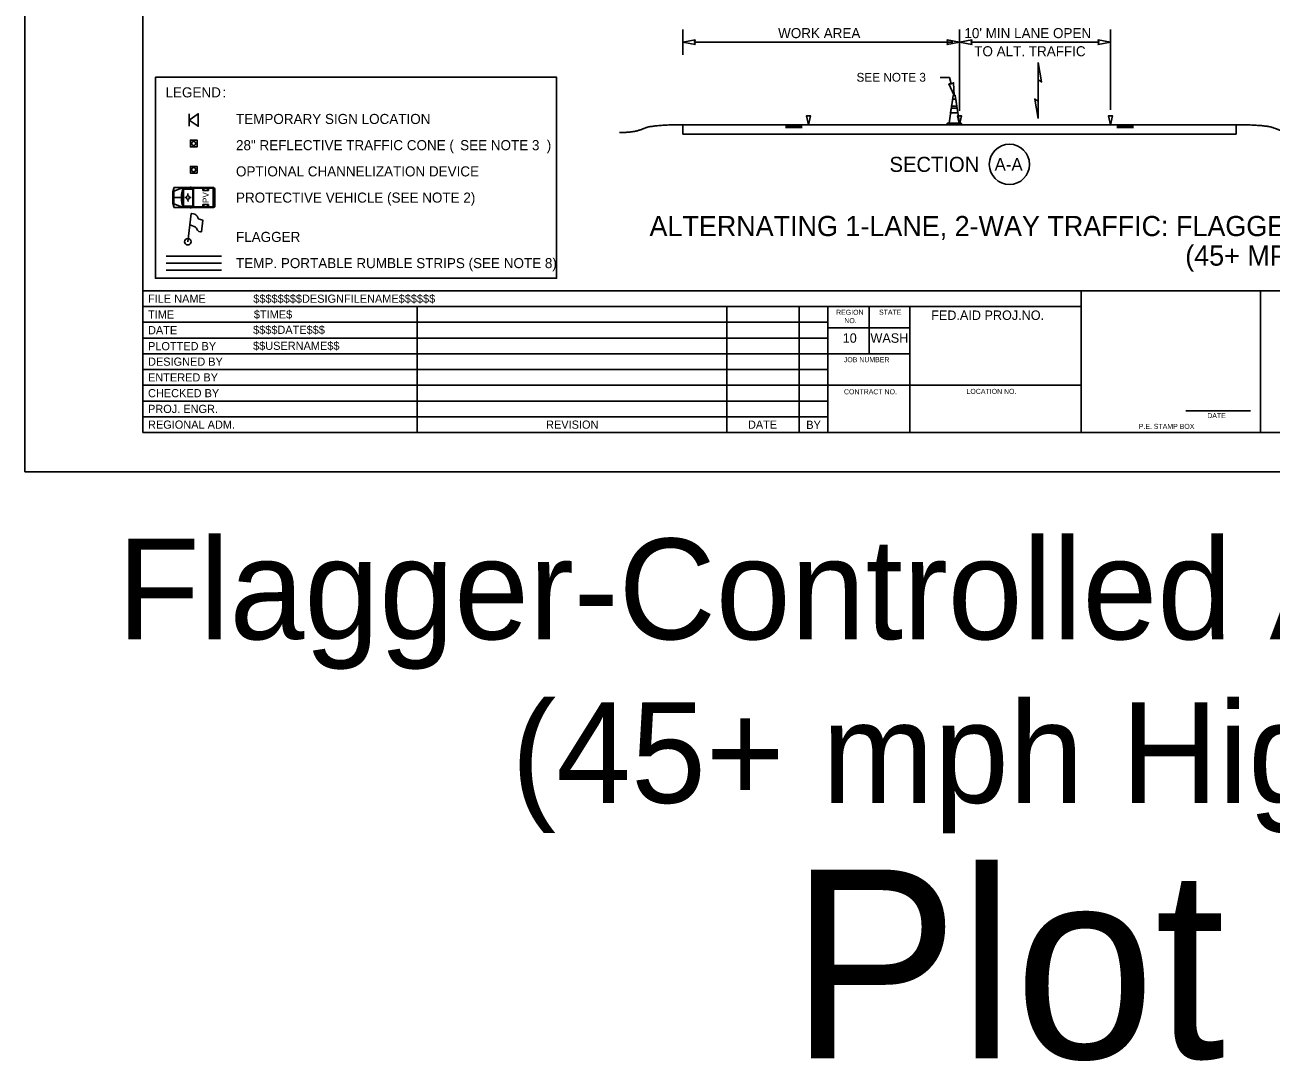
# Model space of a CAD drawing. Extents: x 99999.1 to 100095.7, y 99995 to 100010.7.
# Drawn here: x 99999.06 to 100008.97, y 99995.01 to 100003.24 of the extents above; entities that cross this region are included whole.
import ezdxf

# ---------------------------------------------------------------- set-up
doc = ezdxf.new("R2010")
doc.units = 0
for name, color, linetype in [('SH_DE_DetailHeading1Text', 7, 'Continuous'), ('SH_GI_PlotLimits', 7, 'Continuous'), ('SH_GI_SheetBorder', 7, 'Continuous'), ('SH_GI_SheetLocationText', 7, 'Continuous'), ('SH_GI_SheetTextInCells', 7, 'Continuous'), ('SH_GI_TitleBlockText', 7, 'Continuous'), ('TR_WZ_FlaggingStation', 7, 'Continuous'), ('TR_WZ_PortableSignMountBlk-Org', 7, 'Continuous'), ('TR_WZ_ProtectiveVehicle', 7, 'Continuous'), ('TR_WZ_TrafficCone', 7, 'Continuous'), ('TR_WZ_TrafficConeElev', 7, 'Continuous'), ('TR_WZ_WorkZoneDetails', 7, 'Continuous'), ('TR_WZ_WorkZoneTextCurrent', 7, 'Continuous')]:
    doc.layers.add(name, color=color, linetype=linetype)

msp = doc.modelspace()

# ---------------------------------------------------------------- linework, layer by layer
at = {"layer": 'SH_GI_PlotLimits'}
msp.add_lwpolyline([(99999.0625, 99999.6875), (100016.0625, 99999.6875), (100016.0625, 100010.6875), (99999.0625, 100010.6875)], close=True, dxfattribs=at)
at = {"layer": 'SH_GI_SheetBorder'}
for p, q in [((100000, 100010.375), (100000, 100000)), ((100000, 100001.1259), (100015.75, 100001.1259)), ((100007.4566, 100000), (100007.4566, 100001.1259)), ((100008.8828, 100000), (100008.8828, 100001.1259)), ((100000, 100001.0008), (100007.4566, 100001.0008)), ((100002.179, 100001.0008), (100002.179, 100000)), ((100004.641, 100001.0008), (100004.641, 100000)), ((100005.2164, 100001.0008), (100005.2164, 100000)), ((100005.4451, 100001.0008), (100005.4451, 100000)), ((100005.7719, 100000.6255), (100005.7719, 100001.0008)), ((100006.0956, 100000), (100006.0956, 100001.0008)), ((100000, 100000.8757), (100002.1821, 100000.8757)), ((100002.1821, 100000.8757), (100005.4466, 100000.8757)), ((100006.0958, 100000.831), (100005.4466, 100000.831)), ((100000, 100000.7506), (100002.1821, 100000.7506)), ((100002.1821, 100000.7506), (100005.4466, 100000.7506)), ((100000, 100000.6255), (100005.4466, 100000.6255)), ((100006.0958, 100000.6255), (100005.4466, 100000.6255)), ((100000, 100000.5004), (100005.4466, 100000.5004)), ((100000, 100000.3753), (100005.4466, 100000.3753)), ((100007.4566, 100000.3753), (100005.4466, 100000.3753)), ((100000, 100000.2502), (100005.4466, 100000.2502)), ((100008.2903, 100000.1733), (100008.802, 100000.1733)), ((100000, 100000.1251), (100005.4466, 100000.1251)), ((100000, 100000), (100015.75, 100000))]:
    msp.add_line(p, q, dxfattribs=at)
at = {"layer": 'TR_WZ_FlaggingStation'}
for p, q in [((100000.3571, 100001.5162), (100000.3828, 100001.7409)), ((100000.3723, 100001.6497), (100000.3828, 100001.7412)), ((100000.4771, 100001.6869), (100000.4665, 100001.5932)), ((100000.3723, 100001.6497), (100000.3723, 100001.6497))]:
    msp.add_line(p, q, dxfattribs=at)
for points in [[(100000.3828, 100001.7412), (100000.3874, 100001.7402), (100000.4016, 100001.7374), (100000.4127, 100001.7341), (100000.4204, 100001.7292), (100000.4273, 100001.7254), (100000.4318, 100001.72), (100000.4352, 100001.7137), (100000.4356, 100001.7087), (100000.4399, 100001.7014), (100000.4486, 100001.6954), (100000.4585, 100001.6912), (100000.4771, 100001.6869)], [(100000.4665, 100001.5932), (100000.46, 100001.5943), (100000.4458, 100001.598), (100000.4333, 100001.6064), (100000.4281, 100001.6149), (100000.425, 100001.6231), (100000.4177, 100001.6318), (100000.4089, 100001.6368), (100000.395, 100001.6425), (100000.3723, 100001.6497)]]:
    msp.add_lwpolyline(points, dxfattribs=at)
msp.add_circle((100000.3571, 100001.5162), 0.026, dxfattribs=at)
at = {"layer": 'TR_WZ_PortableSignMountBlk-Org'}
msp.add_line((100000.3682, 100002.433), (100000.3682, 100002.533), dxfattribs=at)
msp.add_lwpolyline([(100000.3682, 100002.4829), (100000.44, 100002.533), (100000.44, 100002.433)], close=True, dxfattribs=at)
at = {"layer": 'TR_WZ_ProtectiveVehicle'}
for p, q in [((100000.245, 100001.9466), (100000.2376, 100001.9143)), ((100000.2376, 100001.9143), (100000.2376, 100001.8189)), ((100000.245, 100001.9466), (100000.245, 100001.7866)), ((100000.245, 100001.9466), (100000.3962, 100001.9466)), ((100000.245, 100001.9173), (100000.3206, 100001.9466)), ((100000.245, 100001.8666), (100000.3058, 100001.8666)), ((100000.3206, 100001.9466), (100000.3206, 100001.7866)), ((100000.322, 100001.9466), (100000.322, 100001.7866)), ((100000.322, 100001.9466), (100000.3316, 100001.9342)), ((100000.322, 100001.9342), (100000.3962, 100001.9342)), ((100000.3341, 100001.8667), (100000.3442, 100001.8667)), ((100000.3582, 100001.8983), (100000.3582, 100001.8854)), ((100000.3695, 100001.8663), (100000.3695, 100001.8663)), ((100000.3829, 100001.866), (100000.371, 100001.8663)), ((100000.3756, 100001.9489), (100000.3846, 100001.9489)), ((100000.3962, 100001.9466), (100000.3962, 100001.7866)), ((100000.5629, 100001.9466), (100000.3984, 100001.9466)), ((100000.3984, 100001.9466), (100000.3984, 100001.7866)), ((100000.5583, 100001.9402), (100000.403, 100001.9402)), ((100000.403, 100001.9402), (100000.403, 100001.793)), ((100000.4772, 100001.9402), (100000.4772, 100001.9218)), ((100000.5212, 100001.9218), (100000.4772, 100001.9218)), ((100000.4852, 100001.9402), (100000.4852, 100001.9218)), ((100000.5124, 100001.9402), (100000.5124, 100001.9218)), ((100000.5212, 100001.9402), (100000.5212, 100001.9218)), ((100000.5583, 100001.9402), (100000.5583, 100001.793)), ((100000.5629, 100001.9466), (100000.5629, 100001.7866)), ((100000.5671, 100001.944), (100000.5635, 100001.944)), ((100000.5635, 100001.944), (100000.5635, 100001.7892)), ((100000.5706, 100001.8779), (100000.5635, 100001.8749)), ((100000.5706, 100001.8553), (100000.5635, 100001.8583)), ((100000.5687, 100001.8666), (100000.5654, 100001.8666)), ((100000.5671, 100001.8689), (100000.5671, 100001.8643)), ((100000.5706, 100001.9391), (100000.5706, 100001.7941)), ((100000.245, 100001.7866), (100000.2376, 100001.8189)), ((100000.245, 100001.8159), (100000.3206, 100001.7866)), ((100000.245, 100001.7866), (100000.3962, 100001.7866)), ((100000.322, 100001.799), (100000.3962, 100001.799)), ((100000.3299, 100001.799), (100000.322, 100001.7866)), ((100000.3588, 100001.8358), (100000.3586, 100001.8479)), ((100000.3756, 100001.7843), (100000.3846, 100001.7843)), ((100000.5629, 100001.7866), (100000.3984, 100001.7866)), ((100000.5583, 100001.793), (100000.403, 100001.793)), ((100000.4772, 100001.793), (100000.4772, 100001.8114)), ((100000.5212, 100001.8114), (100000.4772, 100001.8114)), ((100000.4852, 100001.793), (100000.4852, 100001.8114)), ((100000.5124, 100001.793), (100000.5124, 100001.8114)), ((100000.5212, 100001.793), (100000.5212, 100001.8114)), ((100000.5671, 100001.7892), (100000.5635, 100001.7892))]:
    msp.add_line(p, q, dxfattribs=at)
for centre, major_axis, start_param, end_param in [((100000.4286, 100001.8666), (0, -0.1679), 4.215667, 5.208926), ((100000.5671, 100001.9391), (0, 0.00488), 4.712389, 6.283185), ((100000.5671, 100001.7941), (0, -0.00488), 0, 1.570796)]:
    msp.add_ellipse(centre, major_axis=major_axis, ratio=0.73155, start_param=start_param, end_param=end_param, dxfattribs=at)
for centre, major_axis in [((100000.3582, 100001.8666), (0, 0.0154)), ((100000.5671, 100001.8666), (0, 0.00225))]:
    msp.add_ellipse(centre, major_axis=major_axis, ratio=0.73155, dxfattribs=at)
at = {"layer": 'TR_WZ_TrafficCone'}
for points in [[(100000.3775, 100002.3231), (100000.4308, 100002.3231), (100000.4308, 100002.2698), (100000.3775, 100002.2698), (100000.3775, 100002.3231)], [(100000.3775, 100002.2698), (100000.4308, 100002.2698), (100000.4308, 100002.3231), (100000.3775, 100002.3231), (100000.3775, 100002.2698)], [(100000.3775, 100002.1148), (100000.4308, 100002.1148), (100000.4308, 100002.0615), (100000.3775, 100002.0615), (100000.3775, 100002.1148)], [(100000.3775, 100002.0615), (100000.4308, 100002.0615), (100000.4308, 100002.1148), (100000.3775, 100002.1148), (100000.3775, 100002.0615)]]:
    msp.add_lwpolyline(points, dxfattribs=at)
for centre in [(100000.4041, 100002.2964), (100000.4041, 100002.0881)]:
    msp.add_circle(centre, 0.0167, dxfattribs=at)
at = {"layer": 'TR_WZ_TrafficConeElev'}
for p, q in [((100006.4363, 100002.6476), (100006.428, 100002.5934)), ((100006.4616, 100002.6476), (100006.4363, 100002.6476)), ((100006.4699, 100002.5934), (100006.4616, 100002.6476)), ((100006.4255, 100002.5768), (100006.4197, 100002.5393)), ((100006.4724, 100002.5768), (100006.4255, 100002.5768)), ((100006.428, 100002.5934), (100006.4699, 100002.5934)), ((100006.4782, 100002.5393), (100006.4724, 100002.5768)), ((100006.3953, 100002.458), (100006.3911, 100002.4538)), ((100006.3911, 100002.4538), (100006.3911, 100002.4455)), ((100006.4073, 100002.458), (100006.3953, 100002.458)), ((100006.4197, 100002.5393), (100006.4782, 100002.5393)), ((100006.5068, 100002.4538), (100006.5026, 100002.458)), ((100006.5068, 100002.4455), (100006.5068, 100002.4538)), ((100006.3911, 100002.4455), (100006.5068, 100002.4455))]:
    msp.add_line(p, q, dxfattribs=at)
msp.add_lwpolyline([(100006.4073, 100002.458), (100006.4906, 100002.458), (100006.4568, 100002.6788), (100006.4411, 100002.6788)], close=True, dxfattribs=at)
msp.add_lwpolyline([(100006.4073, 100002.458), (100006.4906, 100002.458), (100006.4568, 100002.6788), (100006.4411, 100002.6788)], close=True, dxfattribs=at)
msp.add_lwpolyline([(100006.5026, 100002.458), (100006.4906, 100002.458), (100006.4073, 100002.458)], dxfattribs=at)
at = {"layer": 'TR_WZ_WorkZoneDetails'}
for p, q in [((100004.2907, 100003.0015), (100004.2907, 100003.2015)), ((100006.4907, 100002.5552), (100006.4907, 100003.2015)), ((100007.6907, 100002.5652), (100007.6907, 100003.2015)), ((100006.4387, 100003.1015), (100004.3844, 100003.1015)), ((100007.597, 100003.1015), (100006.5844, 100003.1015)), ((100006.3358, 100002.8215), (100006.412, 100002.8215)), ((100006.4255, 100002.7696), (100006.412, 100002.8215)), ((100007.1157, 100002.8019), (100007.1157, 100002.6331)), ((100007.1157, 100002.6331), (100007.1157, 100002.8019)), ((100004.2907, 100002.4454), (100004.2907, 100002.3704)), ((100008.6907, 100002.4454), (100004.2907, 100002.4454)), ((100008.6907, 100002.3704), (100004.2907, 100002.3704)), ((100005.1077, 100002.4402), (100005.2407, 100002.4402)), ((100005.1077, 100002.4346), (100005.2407, 100002.4346)), ((100005.1077, 100002.4289), (100005.2407, 100002.4289)), ((100005.1077, 100002.4237), (100005.2407, 100002.4237)), ((100007.8737, 100002.4398), (100007.7407, 100002.4398)), ((100007.8737, 100002.4342), (100007.7407, 100002.4342)), ((100007.8737, 100002.4285), (100007.7407, 100002.4285)), ((100007.8737, 100002.4233), (100007.7407, 100002.4233)), ((100008.6907, 100002.4454), (100008.6907, 100002.3704)), ((100000.6241, 100001.4012), (100000.1841, 100001.4012)), ((100000.6241, 100001.3463), (100000.1841, 100001.3463)), ((100000.6241, 100001.2906), (100000.1841, 100001.2906))]:
    msp.add_line(p, q, dxfattribs=at)
for points in [[(100004.2907, 100003.1015), (100004.389, 100003.0822), (100004.3844, 100003.1015), (100004.389, 100003.1208)], [(100006.4907, 100003.1015), (100006.3924, 100003.0822), (100006.397, 100003.1015), (100006.3924, 100003.1208)], [(100006.4907, 100003.1015), (100006.589, 100003.0822), (100006.5844, 100003.1015), (100006.589, 100003.1208)], [(100007.6907, 100003.1015), (100007.5924, 100003.0822), (100007.597, 100003.1015), (100007.5924, 100003.1208)], [(100007.1157, 100002.9395), (100007.1427, 100002.7863), (100007.1157, 100002.8019)], [(100006.449, 100002.6788), (100006.4057, 100002.7692), (100006.4255, 100002.7696), (100006.443, 100002.7788)], [(100007.1157, 100002.4954), (100007.0887, 100002.6487), (100007.1157, 100002.6331)], [(100005.2907, 100002.4454), (100005.274, 100002.5152), (100005.3073, 100002.5152)], [(100006.4907, 100002.4454), (100006.474, 100002.5152), (100006.5074, 100002.5152)], [(100007.6907, 100002.4454), (100007.674, 100002.5152), (100007.7073, 100002.5152)]]:
    msp.add_lwpolyline(points, close=True, dxfattribs=at)
for points in [[(100005.3073, 100002.5152), (100005.274, 100002.5152), (100005.2907, 100002.4454), (100005.3073, 100002.5152)], [(100006.5074, 100002.5152), (100006.474, 100002.5152), (100006.4907, 100002.4454), (100006.5074, 100002.5152)], [(100007.7073, 100002.5152), (100007.674, 100002.5152), (100007.6907, 100002.4454), (100007.7073, 100002.5152)]]:
    msp.add_lwpolyline(points, dxfattribs=at)
msp.add_circle((100006.8872, 100002.1305), 0.16, dxfattribs=at)
for points in [[(100004.2907, 100002.4454), (100004.0395, 100002.4454), (100003.914, 100002.3833), (100003.7886, 100002.3833)], [(100008.6907, 100002.4454), (100008.9419, 100002.4456), (100009.0674, 100002.3835), (100009.1928, 100002.3836)]]:
    msp.add_open_spline(points, degree=2, dxfattribs=at)
at = {"layer": 'TR_WZ_WorkZoneTextCurrent'}
msp.add_lwpolyline([(100000.1, 100002.8227), (100003.2886, 100002.8227), (100003.2886, 100001.2259), (100000.1, 100001.2259)], close=True, dxfattribs=at)

# ---------------------------------------------------------------- texts
at = {"layer": 'SH_DE_DetailHeading1Text'}
for s, p in [('ALTERNATING 1-LANE, 2-WAY TRAFFIC: FLAGGER-CONTROLLED + TEMPORARY RUMBLE STRIPS', (100004.0265, 100001.5606)), ('(45+ MPH HIGHWAYS)', (100008.2846, 100001.3259))]:
    msp.add_text(s, height=0.16, rotation=360, dxfattribs=at).set_placement(p)
at = {"layer": 'SH_GI_SheetLocationText'}
for s, height, p in [('Flagger-Controlled Alt Traffic + RS', 0.8, (99999.7975, 99998.3571)), ('(45+ mph Highways)', 0.8, (100002.9286, 99997.0571)), ('Plot 1', 1.5, (100005.1448, 99995.0267))]:
    msp.add_text(s, height=height, dxfattribs=at).set_placement(p)
at = {"layer": 'SH_GI_SheetTextInCells'}
for s, height, p in [('FILE NAME', 0.06505, (100000.041, 100001.0308)), ('TIME', 0.06505, (100000.041, 100000.9057)), ('REGION', 0.04003, (100005.5099, 100000.9352)), ('STATE', 0.04003, (100005.8511, 100000.9357)), ('FED.AID PROJ.NO.', 0.07506, (100006.2652, 100000.8945)), ('NO.', 0.04003, (100005.5752, 100000.869)), ('DATE', 0.06505, (100000.041, 100000.7806)), ('10', 0.07506, (100005.5621, 100000.7131)), ('WASH', 0.07506, (100005.7826, 100000.7131)), ('PLOTTED BY', 0.06505, (100000.041, 100000.6538)), ('DESIGNED BY', 0.065052, (100000.041, 100000.5304)), ('JOB NUMBER', 0.04003, (100005.5712, 100000.5587)), ('ENTERED BY', 0.06505, (100000.041, 100000.4053)), ('CHECKED BY', 0.06505, (100000.041, 100000.2802)), ('CONTRACT NO.', 0.040032, (100005.5725, 100000.3037)), ('LOCATION NO.', 0.040032, (100006.5465, 100000.3067)), ('PROJ. ENGR.', 0.065052, (100000.041, 100000.1551)), ('REGIONAL ADM.', 0.065052, (100000.041, 100000.03)), ('REVISION', 0.06505, (100003.2048, 100000.03)), ('DATE', 0.06505, (100004.8091, 100000.03)), ('BY', 0.06505, (100005.2725, 100000.0285)), ('DATE', 0.04003, (100008.4597, 100000.1141)), ('P.E. STAMP BOX', 0.040032, (100007.915, 100000.0286))]:
    msp.add_text(s, height=height, dxfattribs=at).set_placement(p)
at = {"layer": 'SH_GI_TitleBlockText'}
for s, height, p in [('$$$$$$$$DESIGNFILENAME$$$$$$', 0.065052, (100000.8775, 100001.0308)), ('$TIME$', 0.06505, (100000.882, 100000.9059)), ('$$$$DATE$$$', 0.065052, (100000.8759, 100000.7835)), ('$$USERNAME$$', 0.065052, (100000.8759, 100000.6567))]:
    msp.add_text(s, height=height, dxfattribs=at).set_placement(p)
at = {"layer": 'TR_WZ_ProtectiveVehicle'}
msp.add_text('PV', height=0.048, rotation=90, dxfattribs=at).set_placement((100000.5232, 100001.8236))
at = {"layer": 'TR_WZ_WorkZoneDetails'}
for s, p in [('WORK AREA', (100005.0487, 100003.1335)), ("10' MIN LANE OPEN", (100006.5294, 100003.1335)), ('TO ALT. TRAFFIC', (100006.6075, 100002.9895))]:
    msp.add_text(s, height=0.08, dxfattribs=at).set_placement(p)
for s, height, p in [('SECTION', 0.12, (100005.9342, 100002.0705)), ('A-A', 0.1, (100006.7694, 100002.0805))]:
    msp.add_text(s, height=height, rotation=360, dxfattribs=at).set_placement(p)
at = {"layer": 'TR_WZ_WorkZoneTextCurrent'}
msp.add_text('SEE NOTE 3', height=0.07, dxfattribs=at).set_placement((100005.672, 100002.7875))
for s, p in [('LEGEND', (100000.18, 100002.6627)), (':', (100000.6328, 100002.6627)), ('TEMPORARY SIGN LOCATION ', (100000.74, 100002.4514)), ('28" REFLECTIVE TRAFFIC CONE (', (100000.74, 100002.2432)), ('SEE NOTE 3', (100002.5216, 100002.2432)), (')', (100003.2099, 100002.2432)), ('OPTIONAL CHANNELIZATION DEVICE', (100000.74, 100002.0349)), ('PROTECTIVE VEHICLE (SEE NOTE 2)', (100000.74, 100001.8266)), ('FLAGGER', (100000.74, 100001.5142)), ('TEMP. PORTABLE RUMBLE STRIPS (SEE NOTE 8)', (100000.74, 100001.3059))]:
    msp.add_text(s, height=0.08, rotation=360, dxfattribs=at).set_placement(p)

doc.saveas('drawing.dxf')
